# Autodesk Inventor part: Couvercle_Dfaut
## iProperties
Created: 2006-03
Part Number: Couvercle_Dfaut
Document SubType Name: Modeling
Designer: Flavien MARTY
Author: Flavien MARTY
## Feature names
1. Base1
